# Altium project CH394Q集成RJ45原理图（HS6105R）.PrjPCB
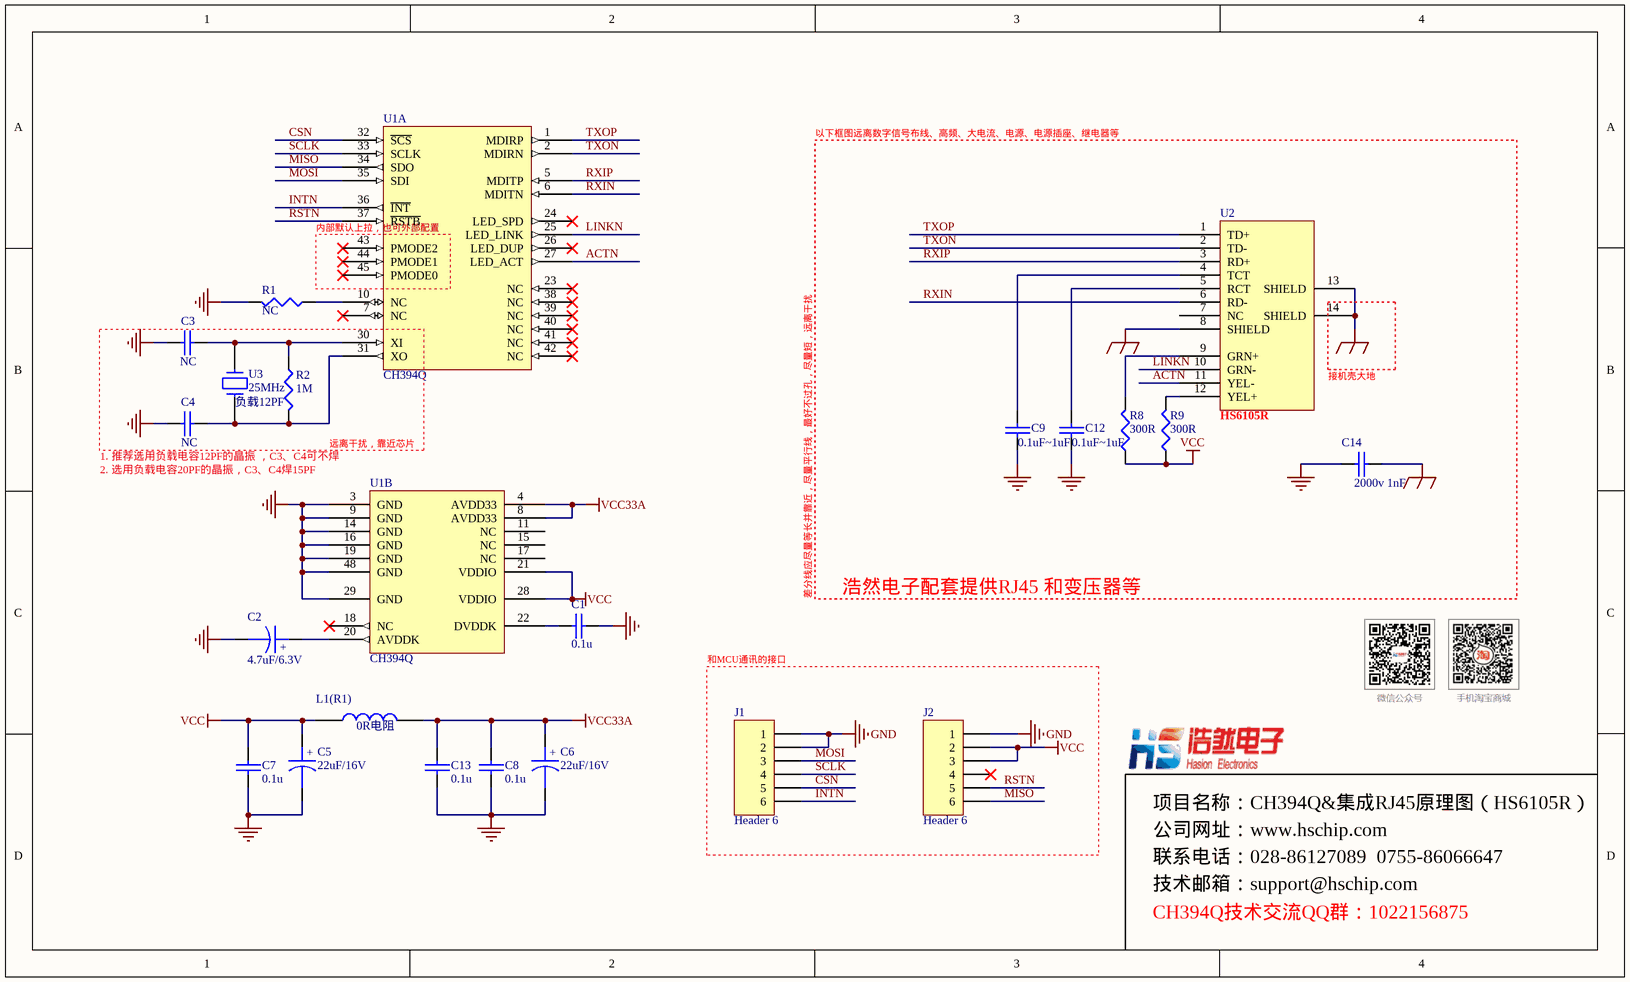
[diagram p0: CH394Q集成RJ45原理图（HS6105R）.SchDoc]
1 sheet, 22 parts. Net scope: global (net labels, ports and power ports of the same name join across sheets).

## Sheet CH394Q集成RJ45原理图（HS6105R）.SchDoc
size 304 x 182 mm; SheetNumber: 0; SheetTotal: 0

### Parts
C1  0.1u  [0603]
C2  4.7uF/6.3V  [3216]
C3  NC  [0603]
C4  NC  [0603]
C5  22uF/16V  [3216]
C6  22uF/16V  [3216]
C7  0.1u  [0603]
C8  0.1u  [0603]
C9  0.1uF~1uF  [0603]
C12  0.1uF~1uF  [0603]
C13  0.1u  [0603]
C14  2000v 1nF  [3216]
J1  Header 6  [SIP6]
J2  Header 6  [SIP6]
L1(R1)  0R电阻  [0603]
R1  NC  [0603]
R2  1M  [0603]
R8  300R  [0603]
R9  300R  [0603]
U1  CH394Q  [LQFP48]  (parts A,B of 2)
U2  HS6105R  [RJ45-1 HS6105R]
U3  25MHz  [XTAL - 49S]

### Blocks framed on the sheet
浩然电子配套提供RJ45 和变压器等: C9 C12 C14 R8 R9 U2
负载12PF: C3 C4 R2 U3
和MCU通讯的接口: J1 J2

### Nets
EARTH: C14.1 U2.8(SHIELD) U2.13(SHIELD) U2.14(SHIELD)
GND: C1.1 C2.2 C3.2 C4.2 C5.2 C6.2 C7.2 C8.2 C9.1 C12.1 C13.2 C14.2 J1.1 J1.2 J2.1 R1.2 U1.3(GND) U1.9(GND) U1.14(GND) U1.16(GND) U1.19(GND) U1.29(GND) U1.48(GND)
VCC: C5.1 C7.1 J2.2 J2.3 L1(R1).1 R8.1 R9.1 U1.21(VDDIO) U1.28(VDDIO)
VCC33A: C6.1 C8.1 C13.1 L1(R1).2 U1.4(AVDD33) U1.8(AVDD33)
ACTN: U1.27(LED_ACT) U2.11(YEL-)
CSN: J1.5 U1.32(~{SCS})
INTN: J1.6 U1.36(~{INT})
LINKN: U1.25(LED_LINK) U2.10(GRN-)
MISO: J2.6 U1.34(SDO)
MOSI: J1.3 U1.35(SDI)
RSTN: J2.5 U1.37(~{RSTB})
RXIN: U1.6(MDITN) U2.6(RD-)
RXIP: U1.5(MDITP) U2.3(RD+)
SCLK: J1.4 U1.33(SCLK)
TXON: U1.2(MDIRN) U2.2(TD-)
TXOP: U1.1(MDIRP) U2.1(TD+)
NetC1_2: C1.2 U1.22(DVDDK)
NetC2_1: C2.1 U1.20(AVDDK)
NetC3_1: C3.1 R2.1 U1.30(XI) U3.1
NetC4_1: C4.1 R2.2 U1.31(XO) U3.2
NetC9_2: C9.2 U2.4(TCT)
NetC12_2: C12.2 U2.5(RCT)
NetR1_1: R1.1 U1.10(NC)
NetR8_2: R8.2 U2.9(GRN+)
NetR9_2: R9.2 U2.12(YEL+)

Not connected (* = marked no-connect by the designer): J2 4*; U1 7(NC)* 11(NC) 15(NC) 17(NC) 18(NC)* 23(NC)* 24(LED_SPD)* 26(LED_DUP)* 38(NC)* 39(NC)* 40(NC)* 41(NC)* 42(NC)* 43(PMODE2)* 44(PMODE1)* 45(PMODE0)*; U2 7(NC)

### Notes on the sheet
- 以下框图远离数字信号布线、高频、大电流、电源、电源插座、继电器等
- (near U1) 内部默认上拉，也可外部配置
- (near U2) 接机壳大地
- (near C4) 1. 推荐选用负载电容12PF的晶振 ，C3、C4可不焊
- 远离干扰，靠近芯片
- (near C4) 2. 选用负载电容20PF的晶振，C3、C4焊15PF
- 差分线应尽量等长并靠近，尽量平行线，最好不过孔，尽量短，远离干扰
- 项目名称：CH394Q&集成RJ45原理图（HS6105R）
- 公司网址：www.hschip.com
- 联系电话：028-86127089  0755-86066647
- CH394Q技术交流QQ群：1022156875
- 技术邮箱：support@hschip.com

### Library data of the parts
C1 C3 C4 C7-C9 C12-C14 = CAP: Capacitor
C2 C5 C6 = CAPACITOR POL: Capacitor
J1 J2 = Header 6: Header, 6-Pin
L1(R1) = INDUCTOR
R1 R2 R8 R9 = RES1
U2 = FC-62115
U3 = CRYSTAL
